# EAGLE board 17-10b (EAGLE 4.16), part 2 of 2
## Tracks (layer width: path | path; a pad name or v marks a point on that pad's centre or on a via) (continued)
S$881  (via drill 1 pad 1.78)
  other vias: 121.92,50.8
S$882  (via drill 1 pad 1.78)
  other vias: 124.46,50.8
S$883  (via drill 1 pad 1.78)
  other vias: 127,50.8
S$884  (via drill 1 pad 1.78)
  other vias: 129.54,50.8
S$885  (via drill 1 pad 1.78)
  other vias: 132.08,50.8
S$886  (via drill 1 pad 1.78)
  other vias: 134.62,50.8
S$887  (via drill 1 pad 1.78)
  other vias: 137.16,50.8
S$888  (via drill 1 pad 1.78)
  other vias: 139.7,50.8
S$889  (via drill 1 pad 1.78)
  other vias: 142.24,50.8
S$890  (via drill 1 pad 1.78)
  other vias: 144.78,50.8
S$891  (via drill 1 pad 1.78)
  other vias: 147.32,50.8
S$892  (via drill 1 pad 1.78)
  other vias: 152.4,50.8
S$893  (via drill 1 pad 1.78)
  other vias: 149.86,50.8
S$894  (via drill 1 pad 1.78)
  other vias: 154.94,50.8
S$895  (via drill 1 pad 1.78)
  other vias: 157.48,50.8
S$896  (via drill 1 pad 1.78)
  other vias: 157.48,48.26
S$897  (via drill 1 pad 1.78)
  other vias: 157.48,45.72
S$898  (via drill 1 pad 1.78)
  other vias: 157.48,43.18
S$899  (via drill 1 pad 1.78)
  other vias: 157.48,40.64
S$900  (via drill 1 pad 1.78)
  other vias: 157.48,38.1
S$901  (via drill 1 pad 1.78)
  other vias: 157.48,35.56
S$902  (via drill 1 pad 1.78)
  other vias: 157.48,33.02
S$903  (via drill 1 pad 1.78)
  other vias: 157.48,27.94
S$904  (via drill 1 pad 1.78)
  other vias: 157.48,30.48
S$905  (via drill 1 pad 1.78)
  other vias: 157.48,25.4
S$906  (via drill 1 pad 1.78)
  other vias: 157.48,22.86
S$907  (via drill 1 pad 1.78)
  other vias: 157.48,20.32
S$908  (via drill 1 pad 1.78)
  other vias: 157.48,17.78
S$909  (via drill 1 pad 1.78)
  other vias: 152.4,17.78
S$910  (via drill 1 pad 1.78)
  other vias: 154.94,17.78
S$911  (via drill 1 pad 1.78)
  other vias: 149.86,17.78
S$912  (via drill 1 pad 1.78)
  other vias: 147.32,17.78
S$913  (via drill 1 pad 1.78)
  other vias: 144.78,17.78
S$914  (via drill 1 pad 1.78)
  other vias: 139.7,17.78
S$915  (via drill 1 pad 1.78)
  other vias: 142.24,17.78
S$916  (via drill 1 pad 1.78)
  other vias: 17.78,48.26
S$917  (via drill 1 pad 1.78)
  other vias: 17.78,45.72
S$918  (via drill 1 pad 1.78)
  other vias: 17.78,43.18
S$919  (via drill 1 pad 1.78)
  other vias: 17.78,40.64
S$920  (via drill 1 pad 1.78)
  other vias: 17.78,38.1
S$921  (via drill 1 pad 1.78)
  other vias: 17.78,35.56
S$922  (via drill 1 pad 1.78)
  other vias: 17.78,30.48
S$923  (via drill 1 pad 1.78)
  other vias: 17.78,33.02
S$924  (via drill 1 pad 1.78)
  other vias: 17.78,27.94
S$925  (via drill 1 pad 1.78)
  other vias: 17.78,25.4
S$926  (via drill 1 pad 1.78)
  other vias: 17.78,22.86
S$927  (via drill 1 pad 1.78)
  other vias: 17.78,20.32
S$928  (via drill 1 pad 1.78)
  other vias: 17.78,17.78
S$929  (via drill 1 pad 1.78)
  other vias: 20.32,17.78
S$930  (via drill 1 pad 1.78)
  other vias: 22.86,17.78
S$931  (via drill 1 pad 1.78)
  other vias: 25.4,17.78
S$932  (via drill 1 pad 1.78)
  other vias: 27.94,17.78
S$933  (via drill 1 pad 1.78)
  other vias: 30.48,17.78
S$934  (via drill 1 pad 1.78)
  other vias: 33.02,17.78
S$935  (via drill 1 pad 1.78)
  other vias: 35.56,17.78
S$936  (via drill 1 pad 1.78)
  other vias: 38.1,17.78
S$937  (via drill 1 pad 1.78)
  other vias: 40.64,17.78
S$938  (via drill 1 pad 1.78)
  other vias: 43.18,17.78
S$939  (via drill 1 pad 1.78)
  other vias: 45.72,17.78
S$940  (via drill 1 pad 1.78)
  other vias: 50.8,17.78
S$941  (via drill 1 pad 1.78)
  other vias: 48.26,17.78
S$942  (via drill 1 pad 1.78)
  other vias: 53.34,17.78
S$943  (via drill 1 pad 1.78)
  other vias: 58.42,17.78
S$944  (via drill 1 pad 1.78)
  other vias: 55.88,17.78
S$945  (via drill 1 pad 1.78)
  other vias: 60.96,17.78
S$946  (via drill 1 pad 1.78)
  other vias: 63.5,17.78
S$947  (via drill 1 pad 1.78)
  other vias: 66.04,17.78
S$948  (via drill 1 pad 1.78)
  other vias: 71.12,17.78
S$949  (via drill 1 pad 1.78)
  other vias: 68.58,17.78
S$950  (via drill 1 pad 1.78)
  other vias: 73.66,17.78
S$951  (via drill 1 pad 1.78)
  other vias: 76.2,17.78
S$952  (via drill 1 pad 1.78)
  other vias: 78.74,17.78
S$953  (via drill 1 pad 1.78)
  other vias: 137.16,17.78
S$954  (via drill 1 pad 1.78)
  other vias: 134.62,17.78
S$955  (via drill 1 pad 1.78)
  other vias: 132.08,17.78
S$956  (via drill 1 pad 1.78)
  other vias: 129.54,17.78
S$957  (via drill 1 pad 1.78)
  other vias: 127,17.78
S$958  (via drill 1 pad 1.78)
  other vias: 124.46,17.78
S$959  (via drill 1 pad 1.78)
  other vias: 121.92,17.78
S$960  (via drill 1 pad 1.78)
  other vias: 119.38,17.78
S$961  (via drill 1 pad 1.78)
  other vias: 116.84,17.78
S$962  (via drill 1 pad 1.78)
  other vias: 114.3,17.78
S$963  (via drill 1 pad 1.78)
  other vias: 111.76,17.78
S$964  (via drill 1 pad 1.78)
  other vias: 106.68,17.78
S$965  (via drill 1 pad 1.78)
  other vias: 109.22,17.78
S$966  (via drill 1 pad 1.78)
  other vias: 104.14,17.78
S$967  (via drill 1 pad 1.78)
  other vias: 101.6,17.78
S$968  (via drill 1 pad 1.78)
  other vias: 99.06,17.78
S$969  (via drill 1 pad 1.78)
  other vias: 96.52,17.78
S$970  (via drill 1 pad 1.78)
  other vias: 93.98,17.78
S$971  (via drill 1 pad 1.78)
  other vias: 91.44,17.78
S$972  (via drill 1 pad 1.78)
  other vias: 88.9,17.78
S$973  (via drill 1 pad 1.78)
  other vias: 86.36,17.78
S$974  (via drill 1 pad 1.78)
  other vias: 83.82,17.78
S$975  (via drill 1 pad 1.78)
  other vias: 81.28,17.78
S$976  (via drill 1 pad 1.78)
  other vias: 154.94,48.26
S$977  (via drill 1 pad 1.78)
  other vias: 154.94,45.72
S$978  (via drill 1 pad 1.78)
  other vias: 154.94,43.18
S$979  (via drill 1 pad 1.78)
  other vias: 154.94,40.64
S$980  (via drill 1 pad 1.78)
  other vias: 154.94,38.1
S$981  (via drill 1 pad 1.78)
  other vias: 154.94,35.56
S$982  (via drill 1 pad 1.78)
  other vias: 154.94,33.02
S$983  (via drill 1 pad 1.78)
  other vias: 154.94,30.48
S$984  (via drill 1 pad 1.78)
  other vias: 154.94,27.94
S$985  (via drill 1 pad 1.78)
  other vias: 154.94,25.4
S$986  (via drill 1 pad 1.78)
  other vias: 154.94,22.86
S$987  (via drill 1 pad 1.78)
  other vias: 154.94,20.32
S$988  (via drill 1 pad 1.78)
  other vias: 48.26,45.72
S$989  (via drill 1 pad 1.78)
  other vias: 48.26,43.18
S$990  (via drill 1 pad 1.78)
  other vias: 48.26,33.02
S$991  (via drill 1 pad 1.78)
  other vias: 55.88,38.1
S$992  (via drill 1 pad 1.78)
  other vias: 60.96,38.1
S$993  (via drill 1 pad 1.78)
  other vias: 63.5,38.1
S$994  (via drill 1 pad 1.78)
  other vias: 66.04,38.1
S$995  (via drill 1 pad 1.78)
  other vias: 71.12,35.56
S$996  (via drill 1 pad 1.78)
  other vias: 86.36,33.02
S$997  (via drill 1 pad 1.78)
  other vias: 88.9,33.02
S$998  (via drill 1 pad 1.78)
  other vias: 91.44,35.56
S$999  (via drill 1 pad 1.78)
  other vias: 132.08,38.1
S$1000  (via drill 1 pad 1.78)
  other vias: 129.54,38.1
S$1001  (via drill 1 pad 1.78)
  other vias: 109.22,33.02
S$1002  (via drill 1 pad 1.78)
  other vias: 114.3,40.64
S$1003  (via drill 1 pad 1.78)
  other vias: 114.3,38.1
S$1004  (via drill 1 pad 1.78)
  other vias: 119.38,27.94
S$1005  (via drill 1 pad 1.78)
  other vias: 127,33.02
S$1006  (via drill 1 pad 1.78)
  other vias: 134.62,30.48
S$1007  (via drill 1 pad 1.78)
  other vias: 139.7,38.1
S$1008  (via drill 1 pad 1.78)
  other vias: 132.08,40.64
S$1009  (via drill 1 pad 1.78)
  other vias: 137.16,43.18
S$1010  (via drill 1 pad 1.78)
  other vias: 144.78,43.18
S$1011  (via drill 1 pad 1.78)
  other vias: 144.78,35.56
S$1012  (via drill 1 pad 1.78)
  other vias: 142.24,30.48
S$1013  (via drill 1 pad 1.78)
  other vias: 132.08,22.86
S$1014  (via drill 1 pad 1.78)
  other vias: 124.46,22.86
S$1015  (via drill 1 pad 1.78)
  other vias: 114.3,22.86
S$1016  (via drill 1 pad 1.78)
  other vias: 116.84,35.56
S$1017  (via drill 1 pad 1.78)
  other vias: 119.38,38.1
S$1018  (via drill 1 pad 1.78)
  other vias: 104.14,43.18
S$1019  (via drill 1 pad 1.78)
  other vias: 93.98,45.72
S$1020  (via drill 1 pad 1.78)
  other vias: 83.82,45.72
S$1021  (via drill 1 pad 1.78)
  other vias: 83.82,40.64
S$1022  (via drill 1 pad 1.78)
  other vias: 73.66,33.02
S$1023  (via drill 1 pad 1.78)
  other vias: 73.66,30.48
S$1024  (via drill 1 pad 1.78)
  other vias: 68.58,30.48
S$1025  (via drill 1 pad 1.78)
  other vias: 63.5,33.02
S$1026  (via drill 1 pad 1.78)
  other vias: 58.42,33.02
S$1027  (via drill 1 pad 1.78)
  other vias: 48.26,27.94
S$1028  (via drill 1 pad 1.78)
  other vias: 45.72,27.94
S$1029  (via drill 1 pad 1.78)
  other vias: 38.1,33.02
S$1030  (via drill 1 pad 1.78)
  other vias: 33.02,30.48
S$1031  (via drill 1 pad 1.78)
  other vias: 27.94,30.48
S$1032  (via drill 1 pad 1.78)
  other vias: 22.86,45.72
S$1033  (via drill 1 pad 1.78)
  other vias: 38.1,43.18
S$1034  (via drill 1 pad 1.78)
  other vias: 33.02,40.64
S$1035  (via drill 1 pad 1.78)
  other vias: 30.48,40.64
S$1036  (via drill 1 pad 1.78)
  other vias: 27.94,40.64
S$1037  (via drill 1 pad 1.78)
  other vias: 22.86,35.56
S$1038  (via drill 1 pad 1.78)
  other vias: 22.86,27.94
S$1039  (via drill 1 pad 1.78)
  other vias: 25.4,22.86
S$1040  (via drill 1 pad 1.78)
  other vias: 33.02,25.4
S$1041  (via drill 1 pad 1.78)
  other vias: 35.56,25.4
S$1042  (via drill 1 pad 1.78)
  other vias: 43.18,30.48
S$1043  (via drill 1 pad 1.78)
  other vias: 45.72,35.56
S$1044  (via drill 1 pad 1.78)
  other vias: 45.72,40.64
S$1045  (via drill 1 pad 1.78)
  other vias: 60.96,40.64
S$1046  (via drill 1 pad 1.78)
  other vias: 66.04,43.18
S$1047  (via drill 1 pad 1.78)
  other vias: 71.12,40.64
S$1048  (via drill 1 pad 1.78)
  other vias: 71.12,38.1
S$1049  (via drill 1 pad 1.78)
  other vias: 73.66,38.1
S$1050  (via drill 1 pad 1.78)
  other vias: 76.2,30.48
S$1051  (via drill 1 pad 1.78)
  other vias: 71.12,25.4
S$1052  (via drill 1 pad 1.78)
  other vias: 78.74,30.48
S$1053  (via drill 1 pad 1.78)
  other vias: 81.28,35.56
S$1054  (via drill 1 pad 1.78)
  other vias: 86.36,30.48
S$1055  (via drill 1 pad 1.78)
  other vias: 88.9,27.94
S$1056  (via drill 1 pad 1.78)
  other vias: 101.6,22.86
S$1057  (via drill 1 pad 1.78)
  other vias: 104.14,25.4
S$1058  (via drill 1 pad 1.78)
  other vias: 104.14,35.56
S$1059  (via drill 1 pad 1.78)
  other vias: 99.06,40.64
S$1060  (via drill 1 pad 1.78)
  other vias: 111.76,43.18
S$1061  (via drill 1 pad 1.78)
  other vias: 129.54,43.18
S$1062  (via drill 1 pad 1.78)
  other vias: 114.3,45.72
S$1063  (via drill 1 pad 1.78)
  other vias: 121.92,43.18
S$1064  (via drill 1 pad 1.78)
  other vias: 124.46,40.64
S$1065  (via drill 1 pad 1.78)
  other vias: 124.46,38.1
S$1066  (via drill 1 pad 1.78)
  other vias: 121.92,33.02
S$1067  (via drill 1 pad 1.78)
  other vias: 124.46,27.94
S$1068  (via drill 1 pad 1.78)
  other vias: 127,27.94
S$1069  (via drill 1 pad 1.78)
  other vias: 129.54,27.94
S$1070  (via drill 1 pad 1.78)
  other vias: 134.62,33.02
S$1071  (via drill 1 pad 1.78)
  other vias: 139.7,33.02
S$1072  (via drill 1 pad 1.78)
  other vias: 144.78,33.02
S$1073  (via drill 1 pad 1.78)
  other vias: 149.86,40.64
S$1074  (via drill 1 pad 1.78)
  other vias: 147.32,27.94
S$1075  (via drill 1 pad 1.78)
  other vias: 142.24,25.4
S$1076  (via drill 1 pad 1.78)
  other vias: 142.24,22.86
S$1077  (via drill 1 pad 1.78)
  other vias: 144.78,22.86
S$1078  (via drill 1 pad 1.78)
  other vias: 147.32,25.4
S$1079  (via drill 1 pad 1.78)
  other vias: 152.4,33.02
S$1080  (via drill 1 pad 1.78)
  other vias: 149.86,35.56
S$1081  (via drill 1 pad 1.78)
  other vias: 134.62,45.72
S$1082  (via drill 1 pad 1.78)
  other vias: 124.46,48.26
S$1083  (via drill 1 pad 1.78)
  other vias: 114.3,48.26
S$1084  (via drill 1 pad 1.78)
  other vias: 106.68,48.26
S$1085  (via drill 1 pad 1.78)
  other vias: 99.06,48.26
S$1086  (via drill 1 pad 1.78)
  other vias: 88.9,45.72
S$1087  (via drill 1 pad 1.78)
  other vias: 88.9,43.18
S$1088  (via drill 1 pad 1.78)
  other vias: 86.36,38.1
S$1089  (via drill 1 pad 1.78)
  other vias: 83.82,35.56
S$1090  (via drill 1 pad 1.78)
  other vias: 81.28,27.94
S$1091  (via drill 1 pad 1.78)
  other vias: 78.74,27.94
S$1092  (via drill 1 pad 1.78)
  other vias: 76.2,25.4
S$1093  (via drill 1 pad 1.78)
  other vias: 68.58,25.4
S$1094  (via drill 1 pad 1.78)
  other vias: 60.96,22.86
S$1095  (via drill 1 pad 1.78)
  other vias: 58.42,22.86
S$1096  (via drill 1 pad 1.78)
  other vias: 55.88,25.4
S$1097  (via drill 1 pad 1.78)
  other vias: 55.88,27.94
S$1098  (via drill 1 pad 1.78)
  other vias: 53.34,33.02
S$1099  (via drill 1 pad 1.78)
  other vias: 53.34,40.64
S$1100  (via drill 1 pad 1.78)
  other vias: 55.88,43.18
S$1101  (via drill 1 pad 1.78)
  other vias: 58.42,43.18
S$1102  (via drill 1 pad 1.78)
  other vias: 58.42,45.72
S$1103  (via drill 1 pad 1.78)
  other vias: 53.34,48.26
S$1104  (via drill 1 pad 1.78)
  other vias: 48.26,48.26
S$1105  (via drill 1 pad 1.78)
  other vias: 43.18,48.26
S$1106  (via drill 1 pad 1.78)
  other vias: 40.64,48.26
S$1107  (via drill 1 pad 1.78)
  other vias: 27.94,45.72
S$1108  (via drill 1 pad 1.78)
  other vias: 30.48,45.72
S$1109  (via drill 1 pad 1.78)
  other vias: 33.02,45.72
S$1110  (via drill 1 pad 1.78)
  other vias: 38.1,38.1
S$1111  (via drill 1 pad 1.78)
  other vias: 27.94,38.1
S$1112  (via drill 1 pad 1.78)
  other vias: 25.4,43.18
S$1113  (via drill 1 pad 1.78)
  other vias: 22.86,40.64
S$1114  (via drill 1 pad 1.78)
  other vias: 25.4,38.1
S$1115  (via drill 1 pad 1.78)
  other vias: 25.4,30.48
S$1116  (via drill 1 pad 1.78)
  other vias: 27.94,22.86
S$1117  (via drill 1 pad 1.78)
  other vias: 30.48,20.32
S$1118  (via drill 1 pad 1.78)
  other vias: 38.1,27.94
S$1119  (via drill 1 pad 1.78)
  other vias: 40.64,25.4
S$1120  (via drill 1 pad 1.78)
  other vias: 45.72,22.86
S$1121  (via drill 1 pad 1.78)
  other vias: 40.64,20.32
S$1122  (via drill 1 pad 1.78)
  other vias: 53.34,22.86
S$1123  (via drill 1 pad 1.78)
  other vias: 45.72,20.32
S$1124  (via drill 1 pad 1.78)
  other vias: 35.56,22.86
S$1125  (via drill 1 pad 1.78)
  other vias: 38.1,22.86
S$1126  (via drill 1 pad 1.78)
  other vias: 48.26,25.4
S$1127  (via drill 1 pad 1.78)
  other vias: 63.5,22.86
S$1128  (via drill 1 pad 1.78)
  other vias: 68.58,22.86
S$1129  (via drill 1 pad 1.78)
  other vias: 71.12,22.86
S$1130  (via drill 1 pad 1.78)
  other vias: 66.04,27.94
S$1131  (via drill 1 pad 1.78)
  other vias: 93.98,22.86
S$1132  (via drill 1 pad 1.78)
  other vias: 96.52,25.4
S$1133  (via drill 1 pad 1.78)
  other vias: 104.14,27.94
S$1134  (via drill 1 pad 1.78)
  other vias: 114.3,27.94
S$1135  (via drill 1 pad 1.78)
  other vias: 111.76,27.94
S$1136  (via drill 1 pad 1.78)
  other vias: 104.14,22.86
S$1137  (via drill 1 pad 1.78)
  other vias: 109.22,25.4
S$1138  (via drill 1 pad 1.78)
  other vias: 109.22,22.86
S$1139  (via drill 1 pad 1.78)
  other vias: 121.92,25.4
S$1140  (via drill 1 pad 1.78)
  other vias: 119.38,22.86
S$1141  (via drill 1 pad 1.78)
  other vias: 137.16,25.4
S$1142  (via drill 1 pad 1.78)
  other vias: 134.62,22.86
S$1143  (via drill 1 pad 1.78)
  other vias: 129.54,25.4
S$1144  (via drill 1 pad 1.78)
  other vias: 127,22.86
S$1145  (via drill 1 pad 1.78)
  other vias: 137.16,22.86
S$1146  (via drill 1 pad 1.78)
  other vias: 149.86,22.86
S$1147  (via drill 1 pad 1.78)
  other vias: 152.4,45.72
S$1148  (via drill 1 pad 1.78)
  other vias: 149.86,45.72
S$1149  (via drill 1 pad 1.78)
  other vias: 147.32,45.72
S$1150  (via drill 1 pad 1.78)
  other vias: 144.78,45.72
S$1151  (via drill 1 pad 1.78)
  other vias: 139.7,48.26
S$1152  (via drill 1 pad 1.78)
  other vias: 109.22,38.1
S$1153  (via drill 1 pad 1.78)
  other vias: 114.3,33.02
S$1154  (via drill 1 pad 1.78)
  other vias: 116.84,30.48
S$1155  (via drill 1 pad 1.78)
  other vias: 132.08,33.02
S$1156  (via drill 1 pad 1.78)
  other vias: 137.16,38.1
S$1157  (via drill 1 pad 1.78)
  other vias: 142.24,43.18
S$1158  (via drill 1 pad 1.78)
  other vias: 147.32,38.1
S$1159  (via drill 1 pad 1.78)
  other vias: 152.4,30.48
S$1160  (via drill 1 pad 1.78)
  other vias: 149.86,30.48
S$1161  (via drill 1 pad 1.78)
  other vias: 152.4,25.4
S$1162  (via drill 1 pad 1.78)
  other vias: 129.54,45.72
S$1163  (via drill 1 pad 1.78)
  other vias: 119.38,45.72
S$1164  (via drill 1 pad 1.78)
  other vias: 116.84,43.18
S$1165  (via drill 1 pad 1.78)
  other vias: 106.68,40.64
S$1166  (via drill 1 pad 1.78)
  other vias: 104.14,38.1
S$1167  (via drill 1 pad 1.78)
  other vias: 99.06,45.72
S$1168  (via drill 1 pad 1.78)
  other vias: 93.98,48.26
S$1169  (via drill 1 pad 1.78)
  other vias: 88.9,48.26
S$1170  (via drill 1 pad 1.78)
  other vias: 81.28,48.26
S$1171  (via drill 1 pad 1.78)
  other vias: 78.74,45.72
S$1172  (via drill 1 pad 1.78)
  other vias: 76.2,40.64
S$1173  (via drill 1 pad 1.78)
  other vias: 76.2,35.56
S$1174  (via drill 1 pad 1.78)
  other vias: 78.74,38.1
S$1175  (via drill 1 pad 1.78)
  other vias: 73.66,43.18
S$1176  (via drill 1 pad 1.78)
  other vias: 73.66,45.72
S$1177  (via drill 1 pad 1.78)
  other vias: 71.12,45.72
S$1178  (via drill 1 pad 1.78)
  other vias: 68.58,45.72
S$1179  (via drill 1 pad 1.78)
  other vias: 60.96,45.72
S$1180  (via drill 1 pad 1.78)
  other vias: 50.8,38.1
S$1181  (via drill 1 pad 1.78)
  other vias: 50.8,43.18
S$1182  (via drill 1 pad 1.78)
  other vias: 50.8,33.02
S$1183  (via drill 1 pad 1.78)
  other vias: 50.8,27.94
S$1184  (via drill 1 pad 1.78)
  other vias: 43.18,43.18
S$1185  (via drill 1 pad 1.78)
  other vias: 43.18,35.56
S$1186  (via drill 1 pad 1.78)
  other vias: 40.64,33.02
S$1187  (via drill 1 pad 1.78)
  other vias: 35.56,40.64
S$1188  (via drill 1 pad 1.78)
  other vias: 35.56,45.72
S$1189  (via drill 1 pad 1.78)
  other vias: 152.4,20.32
S$1190  (via drill 1 pad 1.78)
  other vias: 149.86,20.32
S$1191  (via drill 1 pad 1.78)
  other vias: 147.32,20.32
S$1192  (via drill 1 pad 1.78)
  other vias: 139.7,20.32
S$1193  (via drill 1 pad 1.78)
  other vias: 134.62,20.32
S$1194  (via drill 1 pad 1.78)
  other vias: 132.08,20.32
S$1195  (via drill 1 pad 1.78)
  other vias: 127,20.32
S$1196  (via drill 1 pad 1.78)
  other vias: 124.46,20.32
S$1197  (via drill 1 pad 1.78)
  other vias: 114.3,20.32
S$1198  (via drill 1 pad 1.78)
  other vias: 111.76,20.32
S$1199  (via drill 1 pad 1.78)
  other vias: 104.14,20.32
S$1200  (via drill 1 pad 1.78)
  other vias: 99.06,20.32
S$1201  (via drill 1 pad 1.78)
  other vias: 93.98,20.32
S$1202  (via drill 1 pad 1.78)
  other vias: 91.44,20.32
S$1203  (via drill 1 pad 1.78)
  other vias: 88.9,20.32
S$1204  (via drill 1 pad 1.78)
  other vias: 86.36,20.32
S$1205  (via drill 1 pad 1.78)
  other vias: 83.82,20.32
S$1206  (via drill 1 pad 1.78)
  other vias: 81.28,20.32
S$1207  (via drill 1 pad 1.78)
  other vias: 48.26,20.32
S$1208  (via drill 1 pad 1.78)
  other vias: 50.8,20.32
S$1209  (via drill 1 pad 1.78)
  other vias: 53.34,20.32
S$1210  (via drill 1 pad 1.78)
  other vias: 58.42,20.32
S$1211  (via drill 1 pad 1.78)
  other vias: 60.96,20.32
S$1212  (via drill 1 pad 1.78)
  other vias: 63.5,20.32
S$1213  (via drill 1 pad 1.78)
  other vias: 66.04,20.32
S$1214  (via drill 1 pad 1.78)
  other vias: 68.58,20.32
S$1215  (via drill 1 pad 1.78)
  other vias: 73.66,20.32
S$1216  (via drill 1 pad 1.78)
  other vias: 76.2,20.32
S$1217  (via drill 1 pad 1.78)
  other vias: 78.74,22.86
S$1218  (via drill 1 pad 1.78)
  other vias: 83.82,25.4
S$1219  (via drill 1 pad 1.78)
  other vias: 86.36,27.94
S$1220  (via drill 1 pad 1.78)
  other vias: 91.44,25.4
S$1221  (via drill 1 pad 1.78)
  other vias: 91.44,30.48
S$1222  (via drill 1 pad 1.78)
  other vias: 93.98,33.02
S$1223  (via drill 1 pad 1.78)
  other vias: 96.52,35.56
S$1224  (via drill 1 pad 1.78)
  other vias: 101.6,27.94
S$1225  (via drill 1 pad 1.78)
  other vias: 101.6,30.48
S$1226  (via drill 1 pad 1.78)
  other vias: 101.6,33.02
S$1227  (via drill 1 pad 1.78)
  other vias: 106.68,30.48
S$1228  (via drill 1 pad 1.78)
  other vias: 106.68,27.94
S$1229  (via drill 1 pad 1.78)
  other vias: 106.68,25.4
S$1230  (via drill 1 pad 1.78)
  other vias: 109.22,20.32
S$1231  (via drill 1 pad 1.78)
  other vias: 114.3,25.4
S$1232  (via drill 1 pad 1.78)
  other vias: 111.76,22.86
S$1233  (via drill 1 pad 1.78)
  other vias: 111.76,25.4
S$1234  (via drill 1 pad 1.78)
  other vias: 116.84,25.4
S$1235  (via drill 1 pad 1.78)
  other vias: 116.84,20.32
S$1236  (via drill 1 pad 1.78)
  other vias: 116.84,22.86
S$1237  (via drill 1 pad 1.78)
  other vias: 119.38,20.32
S$1238  (via drill 1 pad 1.78)
  other vias: 121.92,20.32
S$1239  (via drill 1 pad 1.78)
  other vias: 121.92,22.86
S$1240  (via drill 1 pad 1.78)
  other vias: 129.54,22.86
S$1241  (via drill 1 pad 1.78)
  other vias: 129.54,20.32
S$1242  (via drill 1 pad 1.78)
  other vias: 137.16,20.32
S$1243  (via drill 1 pad 1.78)
  other vias: 142.24,20.32
S$1244  (via drill 1 pad 1.78)
  other vias: 144.78,20.32
S$1245  (via drill 1 pad 1.78)
  other vias: 152.4,22.86
S$1246  (via drill 1 pad 1.78)
  other vias: 152.4,27.94
S$1247  (via drill 1 pad 1.78)
  other vias: 152.4,48.26
S$1248  (via drill 1 pad 1.78)
  other vias: 152.4,43.18
S$1249  (via drill 1 pad 1.78)
  other vias: 152.4,40.64
S$1250  (via drill 1 pad 1.78)
  other vias: 152.4,38.1
S$1251  (via drill 1 pad 1.78)
  other vias: 152.4,35.56
S$1252  (via drill 1 pad 1.78)
  other vias: 149.86,48.26
S$1253  (via drill 1 pad 1.78)
  other vias: 147.32,48.26
S$1254  (via drill 1 pad 1.78)
  other vias: 144.78,48.26
S$1255  (via drill 1 pad 1.78)
  other vias: 142.24,48.26
S$1256  (via drill 1 pad 1.78)
  other vias: 137.16,48.26
S$1257  (via drill 1 pad 1.78)
  other vias: 134.62,48.26
S$1258  (via drill 1 pad 1.78)
  other vias: 129.54,48.26
S$1259  (via drill 1 pad 1.78)
  other vias: 127,48.26
S$1260  (via drill 1 pad 1.78)
  other vias: 121.92,48.26
S$1261  (via drill 1 pad 1.78)
  other vias: 119.38,48.26
S$1262  (via drill 1 pad 1.78)
  other vias: 116.84,48.26
S$1263  (via drill 1 pad 1.78)
  other vias: 116.84,45.72
S$1264  (via drill 1 pad 1.78)
  other vias: 116.84,40.64
S$1265  (via drill 1 pad 1.78)
  other vias: 116.84,38.1
S$1266  (via drill 1 pad 1.78)
  other vias: 119.38,43.18
S$1267  (via drill 1 pad 1.78)
  other vias: 121.92,40.64
S$1268  (via drill 1 pad 1.78)
  other vias: 119.38,40.64
S$1269  (via drill 1 pad 1.78)
  other vias: 124.46,45.72
S$1270  (via drill 1 pad 1.78)
  other vias: 121.92,45.72
S$1271  (via drill 1 pad 1.78)
  other vias: 127,45.72
S$1272  (via drill 1 pad 1.78)
  other vias: 124.46,43.18
S$1273  (via drill 1 pad 1.78)
  other vias: 127,43.18
S$1274  (via drill 1 pad 1.78)
  other vias: 127,40.64
S$1275  (via drill 1 pad 1.78)
  other vias: 127,38.1
S$1276  (via drill 1 pad 1.78)
  other vias: 20.32,48.26
S$1277  (via drill 1 pad 1.78)
  other vias: 20.32,45.72
S$1278  (via drill 1 pad 1.78)
  other vias: 20.32,43.18
S$1279  (via drill 1 pad 1.78)
  other vias: 20.32,40.64
S$1280  (via drill 1 pad 1.78)
  other vias: 20.32,38.1
S$1281  (via drill 1 pad 1.78)
  other vias: 20.32,35.56
S$1282  (via drill 1 pad 1.78)
  other vias: 20.32,33.02
S$1283  (via drill 1 pad 1.78)
  other vias: 20.32,30.48
S$1284  (via drill 1 pad 1.78)
  other vias: 20.32,27.94
S$1285  (via drill 1 pad 1.78)
  other vias: 20.32,25.4
S$1286  (via drill 1 pad 1.78)
  other vias: 20.32,22.86
S$1287  (via drill 1 pad 1.78)
  other vias: 20.32,20.32
S$1288  (via drill 1 pad 1.78)
  other vias: 22.86,20.32
S$1289  (via drill 1 pad 1.78)
  other vias: 25.4,20.32
S$1290  (via drill 1 pad 1.78)
  other vias: 27.94,20.32
S$1291  (via drill 1 pad 1.78)
  other vias: 22.86,22.86
S$1292  (via drill 1 pad 1.78)
  other vias: 22.86,33.02
S$1293  (via drill 1 pad 1.78)
  other vias: 22.86,25.4
S$1294  (via drill 1 pad 1.78)
  other vias: 22.86,30.48
S$1295  (via drill 1 pad 1.78)
  other vias: 22.86,38.1
S$1296  (via drill 1 pad 1.78)
  other vias: 22.86,43.18
S$1297  (via drill 1 pad 1.78)
  other vias: 22.86,48.26
S$1298  (via drill 1 pad 1.78)
  other vias: 27.94,48.26
S$1299  (via drill 1 pad 1.78)
  other vias: 30.48,48.26
S$1300  (via drill 1 pad 1.78)
  other vias: 33.02,48.26
S$1301  (via drill 1 pad 1.78)
  other vias: 35.56,48.26
S$1302  (via drill 1 pad 1.78)
  other vias: 27.94,43.18
S$1303  (via drill 1 pad 1.78)
  other vias: 25.4,40.64
S$1304  (via drill 1 pad 1.78)
  other vias: 25.4,35.56
S$1305  (via drill 1 pad 1.78)
  other vias: 25.4,33.02
S$1306  (via drill 1 pad 1.78)
  other vias: 25.4,27.94
S$1307  (via drill 1 pad 1.78)
  other vias: 25.4,25.4
S$1308  (via drill 1 pad 1.78)
  other vias: 27.94,25.4
S$1309  (via drill 1 pad 1.78)
  other vias: 27.94,27.94
S$1310  (via drill 1 pad 1.78)
  other vias: 27.94,35.56
S$1311  (via drill 1 pad 1.78)
  other vias: 30.48,38.1
S$1312  (via drill 1 pad 1.78)
  other vias: 30.48,43.18
S$1313  (via drill 1 pad 1.78)
  other vias: 33.02,43.18
S$1314  (via drill 1 pad 1.78)
  other vias: 35.56,43.18
S$1315  (via drill 1 pad 1.78)
  other vias: 33.02,38.1
S$1316  (via drill 1 pad 1.78)
  other vias: 35.56,38.1
S$1317  (via drill 1 pad 1.78)
  other vias: 33.02,35.56
S$1318  (via drill 1 pad 1.78)
  other vias: 30.48,35.56
S$1319  (via drill 1 pad 1.78)
  other vias: 35.56,33.02
S$1320  (via drill 1 pad 1.78)
  other vias: 33.02,33.02
S$1321  (via drill 1 pad 1.78)
  other vias: 30.48,30.48
S$1322  (via drill 1 pad 1.78)
  other vias: 30.48,27.94
S$1323  (via drill 1 pad 1.78)
  other vias: 30.48,25.4
S$1324  (via drill 1 pad 1.78)
  other vias: 30.48,22.86
S$1325  (via drill 1 pad 1.78)
  other vias: 33.02,20.32
S$1326  (via drill 1 pad 1.78)
  other vias: 35.56,20.32
S$1327  (via drill 1 pad 1.78)
  other vias: 38.1,20.32
S$1328  (via drill 1 pad 1.78)
  other vias: 33.02,22.86
S$1329  (via drill 1 pad 1.78)
  other vias: 33.02,27.94
S$1330  (via drill 1 pad 1.78)
  other vias: 35.56,27.94
S$1331  (via drill 1 pad 1.78)
  other vias: 35.56,30.48
S$1332  (via drill 1 pad 1.78)
  other vias: 38.1,30.48
S$1333  (via drill 1 pad 1.78)
  other vias: 40.64,30.48
S$1334  (via drill 1 pad 1.78)
  other vias: 40.64,27.94
S$1335  (via drill 1 pad 1.78)
  other vias: 43.18,27.94
S$1336  (via drill 1 pad 1.78)
  other vias: 43.18,25.4
S$1337  (via drill 1 pad 1.78)
  other vias: 45.72,25.4
S$1338  (via drill 1 pad 1.78)
  other vias: 43.18,22.86
S$1339  (via drill 1 pad 1.78)
  other vias: 43.18,20.32
S$1340  (via drill 1 pad 1.78)
  other vias: 40.64,22.86
S$1341  (via drill 1 pad 1.78)
  other vias: 38.1,25.4
S$1342  (via drill 1 pad 1.78)
  other vias: 38.1,48.26
S$1343  (via drill 1 pad 1.78)
  other vias: 38.1,45.72
S$1344  (via drill 1 pad 1.78)
  other vias: 38.1,40.64
S$1345  (via drill 1 pad 1.78)
  other vias: 38.1,35.56
S$1346  (via drill 1 pad 1.78)
  other vias: 40.64,45.72
S$1347  (via drill 1 pad 1.78)
  other vias: 40.64,43.18
S$1348  (via drill 1 pad 1.78)
  other vias: 45.72,48.26
S$1349  (via drill 1 pad 1.78)
  other vias: 55.88,48.26
S$1350  (via drill 1 pad 1.78)
  other vias: 50.8,48.26
S$1351  (via drill 1 pad 1.78)
  other vias: 45.72,45.72
S$1352  (via drill 1 pad 1.78)
  other vias: 43.18,45.72
S$1353  (via drill 1 pad 1.78)
  other vias: 45.72,43.18
S$1354  (via drill 1 pad 1.78)
  other vias: 43.18,40.64
S$1355  (via drill 1 pad 1.78)
  other vias: 40.64,40.64
S$1356  (via drill 1 pad 1.78)
  other vias: 43.18,38.1
S$1357  (via drill 1 pad 1.78)
  other vias: 40.64,35.56
S$1358  (via drill 1 pad 1.78)
  other vias: 43.18,33.02
S$1359  (via drill 1 pad 1.78)
  other vias: 45.72,33.02
S$1360  (via drill 1 pad 1.78)
  other vias: 45.72,38.1
S$1361  (via drill 1 pad 1.78)
  other vias: 58.42,48.26
S$1362  (via drill 1 pad 1.78)
  other vias: 63.5,48.26
S$1363  (via drill 1 pad 1.78)
  other vias: 60.96,48.26
S$1364  (via drill 1 pad 1.78)
  other vias: 66.04,48.26
S$1365  (via drill 1 pad 1.78)
  other vias: 68.58,48.26
S$1366  (via drill 1 pad 1.78)
  other vias: 73.66,48.26
S$1367  (via drill 1 pad 1.78)
  other vias: 76.2,48.26
S$1368  (via drill 1 pad 1.78)
  other vias: 78.74,48.26
S$1369  (via drill 1 pad 1.78)
  other vias: 83.82,48.26
S$1370  (via drill 1 pad 1.78)
  other vias: 86.36,48.26
S$1371  (via drill 1 pad 1.78)
  other vias: 86.36,45.72
S$1372  (via drill 1 pad 1.78)
  other vias: 86.36,43.18
S$1373  (via drill 1 pad 1.78)
  other vias: 86.36,40.64
S$1374  (via drill 1 pad 1.78)
  other vias: 83.82,43.18
S$1375  (via drill 1 pad 1.78)
  other vias: 81.28,43.18
S$1376  (via drill 1 pad 1.78)
  other vias: 81.28,45.72
S$1377  (via drill 1 pad 1.78)
  other vias: 76.2,45.72
S$1378  (via drill 1 pad 1.78)
  other vias: 78.74,43.18
S$1379  (via drill 1 pad 1.78)
  other vias: 76.2,43.18
S$1380  (via drill 1 pad 1.78)
  other vias: 71.12,43.18
S$1381  (via drill 1 pad 1.78)
  other vias: 68.58,43.18
S$1382  (via drill 1 pad 1.78)
  other vias: 66.04,45.72
S$1383  (via drill 1 pad 1.78)
  other vias: 63.5,45.72
S$1384  (via drill 1 pad 1.78)
  other vias: 63.5,43.18
S$1385  (via drill 1 pad 1.78)
  other vias: 60.96,43.18
S$1386  (via drill 1 pad 1.78)
  other vias: 55.88,45.72
S$1387  (via drill 1 pad 1.78)
  other vias: 53.34,45.72
S$1388  (via drill 1 pad 1.78)
  other vias: 50.8,45.72
S$1389  (via drill 1 pad 1.78)
  other vias: 53.34,43.18
S$1390  (via drill 1 pad 1.78)
  other vias: 48.26,40.64
S$1391  (via drill 1 pad 1.78)
  other vias: 48.26,38.1
S$1392  (via drill 1 pad 1.78)
  other vias: 48.26,35.56
S$1393  (via drill 1 pad 1.78)
  other vias: 50.8,35.56
S$1394  (via drill 1 pad 1.78)
  other vias: 53.34,35.56
S$1395  (via drill 1 pad 1.78)
  other vias: 58.42,35.56
S$1396  (via drill 1 pad 1.78)
  other vias: 66.04,35.56
S$1397  (via drill 1 pad 1.78)
  other vias: 139.7,22.86
S$1398  (via drill 1 pad 1.78)
  other vias: 147.32,22.86
S$1399  (via drill 1 pad 1.78)
  other vias: 149.86,25.4
S$1400  (via drill 1 pad 1.78)
  other vias: 149.86,27.94
S$1401  (via drill 1 pad 1.78)
  other vias: 144.78,25.4
S$1402  (via drill 1 pad 1.78)
  other vias: 144.78,27.94
S$1403  (via drill 1 pad 1.78)
  other vias: 147.32,30.48
S$1404  (via drill 1 pad 1.78)
  other vias: 149.86,33.02
S$1405  (via drill 1 pad 1.78)
  other vias: 147.32,33.02
S$1406  (via drill 1 pad 1.78)
  other vias: 147.32,35.56
S$1407  (via drill 1 pad 1.78)
  other vias: 149.86,38.1
S$1408  (via drill 1 pad 1.78)
  other vias: 149.86,43.18
S$1409  (via drill 1 pad 1.78)
  other vias: 147.32,43.18
S$1410  (via drill 1 pad 1.78)
  other vias: 147.32,40.64
S$1411  (via drill 1 pad 1.78)
  other vias: 144.78,40.64
S$1412  (via drill 1 pad 1.78)
  other vias: 142.24,40.64
S$1413  (via drill 1 pad 1.78)
  other vias: 91.44,48.26
S$1414  (via drill 1 pad 1.78)
  other vias: 96.52,48.26
S$1415  (via drill 1 pad 1.78)
  other vias: 101.6,48.26
S$1416  (via drill 1 pad 1.78)
  other vias: 104.14,48.26
S$1417  (via drill 1 pad 1.78)
  other vias: 101.6,45.72
S$1418  (via drill 1 pad 1.78)
  other vias: 101.6,40.64
S$1419  (via drill 1 pad 1.78)
  other vias: 101.6,38.1
S$1420  (via drill 1 pad 1.78)
  other vias: 99.06,38.1
S$1421  (via drill 1 pad 1.78)
  other vias: 96.52,38.1
S$1422  (via drill 1 pad 1.78)
  other vias: 93.98,38.1
S$1423  (via drill 1 pad 1.78)
  other vias: 91.44,38.1
S$1424  (via drill 1 pad 1.78)
  other vias: 88.9,40.64
S$1425  (via drill 1 pad 1.78)
  other vias: 91.44,40.64
S$1426  (via drill 1 pad 1.78)
  other vias: 91.44,43.18
S$1427  (via drill 1 pad 1.78)
  other vias: 93.98,43.18
S$1428  (via drill 1 pad 1.78)
  other vias: 96.52,43.18
S$1429  (via drill 1 pad 1.78)
  other vias: 99.06,43.18
S$1430  (via drill 1 pad 1.78)
  other vias: 101.6,43.18
S$1431  (via drill 1 pad 1.78)
  other vias: 109.22,48.26
S$1432  (via drill 1 pad 1.78)
  other vias: 109.22,45.72
S$1433  (via drill 1 pad 1.78)
  other vias: 109.22,43.18
S$1434  (via drill 1 pad 1.78)
  other vias: 109.22,40.64
S$1435  (via drill 1 pad 1.78)
  other vias: 111.76,40.64
S$1436  (via drill 1 pad 1.78)
  other vias: 111.76,38.1
S$1437  (via drill 1 pad 1.78)
  other vias: 111.76,35.56
S$1438  (via drill 1 pad 1.78)
  other vias: 111.76,30.48
S$1439  (via drill 1 pad 1.78)
  other vias: 111.76,33.02
S$1440  (via drill 1 pad 1.78)
  other vias: 76.2,33.02
S$1441  (via drill 1 pad 1.78)
  other vias: 78.74,33.02
S$1442  (via drill 1 pad 1.78)
  other vias: 81.28,33.02
S$1443  (via drill 1 pad 1.78)
  other vias: 83.82,33.02
S$1444  (via drill 1 pad 1.78)
  other vias: 83.82,30.48
S$1445  (via drill 1 pad 1.78)
  other vias: 83.82,27.94
S$1446  (via drill 1 pad 1.78)
  other vias: 45.72,30.48
S$1447  (via drill 1 pad 1.78)
  other vias: 48.26,30.48
S$1448  (via drill 1 pad 1.78)
  other vias: 50.8,30.48
S$1449  (via drill 1 pad 1.78)
  other vias: 53.34,30.48
S$1450  (via drill 1 pad 1.78)
  other vias: 58.42,30.48
S$1451  (via drill 1 pad 1.78)
  other vias: 60.96,30.48
S$1452  (via drill 1 pad 1.78)
  other vias: 63.5,30.48
S$1453  (via drill 1 pad 1.78)
  other vias: 66.04,30.48
S$1454  (via drill 1 pad 1.78)
  other vias: 55.88,30.48
S$1455  (via drill 1 pad 1.78)
  other vias: 55.88,33.02
S$1456  (via drill 1 pad 1.78)
  other vias: 58.42,40.64
S$1457  (via drill 1 pad 1.78)
  other vias: 55.88,40.64
S$1458  (via drill 1 pad 1.78)
  other vias: 50.8,40.64
S$1459  (via drill 1 pad 1.78)
  other vias: 53.34,38.1
S$1460  (via drill 1 pad 1.78)
  other vias: 58.42,38.1
S$1461  (via drill 1 pad 1.78)
  other vias: 63.5,40.64
S$1462  (via drill 1 pad 1.78)
  other vias: 66.04,40.64
S$1463  (via drill 1 pad 1.78)
  other vias: 68.58,40.64
S$1464  (via drill 1 pad 1.78)
  other vias: 68.58,38.1
S$1465  (via drill 1 pad 1.78)
  other vias: 68.58,35.56
S$1466  (via drill 1 pad 1.78)
  other vias: 48.26,22.86
S$1467  (via drill 1 pad 1.78)
  other vias: 50.8,22.86
S$1468  (via drill 1 pad 1.78)
  other vias: 50.8,25.4
S$1469  (via drill 1 pad 1.78)
  other vias: 53.34,25.4
S$1470  (via drill 1 pad 1.78)
  other vias: 53.34,27.94
S$1471  (via drill 1 pad 1.78)
  other vias: 55.88,35.56
S$1472  (via drill 1 pad 1.78)
  other vias: 55.88,22.86
S$1473  (via drill 1 pad 1.78)
  other vias: 55.88,20.32
S$1474  (via drill 1 pad 1.78)
  other vias: 58.42,25.4
S$1475  (via drill 1 pad 1.78)
  other vias: 60.96,25.4
S$1476  (via drill 1 pad 1.78)
  other vias: 63.5,25.4
S$1477  (via drill 1 pad 1.78)
  other vias: 66.04,25.4
S$1478  (via drill 1 pad 1.78)
  other vias: 66.04,22.86
S$1479  (via drill 1 pad 1.78)
  other vias: 63.5,27.94
S$1480  (via drill 1 pad 1.78)
  other vias: 58.42,27.94
S$1481  (via drill 1 pad 1.78)
  other vias: 60.96,33.02
S$1482  (via drill 1 pad 1.78)
  other vias: 60.96,35.56
S$1483  (via drill 1 pad 1.78)
  other vias: 63.5,35.56
S$1484  (via drill 1 pad 1.78)
  other vias: 66.04,33.02
S$1485  (via drill 1 pad 1.78)
  other vias: 68.58,33.02
S$1486  (via drill 1 pad 1.78)
  other vias: 71.12,33.02
S$1487  (via drill 1 pad 1.78)
  other vias: 71.12,30.48
S$1488  (via drill 1 pad 1.78)
  other vias: 71.12,27.94
S$1489  (via drill 1 pad 1.78)
  other vias: 68.58,27.94
S$1490  (via drill 1 pad 1.78)
  other vias: 71.12,20.32
S$1491  (via drill 1 pad 1.78)
  other vias: 73.66,22.86
S$1492  (via drill 1 pad 1.78)
  other vias: 76.2,22.86
S$1493  (via drill 1 pad 1.78)
  other vias: 73.66,25.4
S$1494  (via drill 1 pad 1.78)
  other vias: 73.66,27.94
S$1495  (via drill 1 pad 1.78)
  other vias: 76.2,27.94
S$1496  (via drill 1 pad 1.78)
  other vias: 73.66,35.56
S$1497  (via drill 1 pad 1.78)
  other vias: 73.66,40.64
S$1498  (via drill 1 pad 1.78)
  other vias: 76.2,38.1
S$1499  (via drill 1 pad 1.78)
  other vias: 78.74,40.64
S$1500  (via drill 1 pad 1.78)
  other vias: 78.74,35.56
S$1501  (via drill 1 pad 1.78)
  other vias: 81.28,38.1
S$1502  (via drill 1 pad 1.78)
  other vias: 83.82,38.1
S$1503  (via drill 1 pad 1.78)
  other vias: 91.44,45.72
S$1504  (via drill 1 pad 1.78)
  other vias: 96.52,45.72
S$1505  (via drill 1 pad 1.78)
  other vias: 104.14,45.72
S$1506  (via drill 1 pad 1.78)
  other vias: 111.76,48.26
S$1507  (via drill 1 pad 1.78)
  other vias: 111.76,45.72
S$1508  (via drill 1 pad 1.78)
  other vias: 106.68,45.72
S$1509  (via drill 1 pad 1.78)
  other vias: 106.68,43.18
S$1510  (via drill 1 pad 1.78)
  other vias: 104.14,40.64
S$1511  (via drill 1 pad 1.78)
  other vias: 96.52,40.64
S$1512  (via drill 1 pad 1.78)
  other vias: 88.9,38.1
S$1513  (via drill 1 pad 1.78)
  other vias: 88.9,35.56
S$1514  (via drill 1 pad 1.78)
  other vias: 86.36,35.56
S$1515  (via drill 1 pad 1.78)
  other vias: 81.28,30.48
S$1516  (via drill 1 pad 1.78)
  other vias: 81.28,25.4
S$1517  (via drill 1 pad 1.78)
  other vias: 78.74,25.4
S$1518  (via drill 1 pad 1.78)
  other vias: 81.28,22.86
S$1519  (via drill 1 pad 1.78)
  other vias: 83.82,22.86
S$1520  (via drill 1 pad 1.78)
  other vias: 86.36,25.4
S$1521  (via drill 1 pad 1.78)
  other vias: 88.9,25.4
S$1522  (via drill 1 pad 1.78)
  other vias: 88.9,22.86
S$1523  (via drill 1 pad 1.78)
  other vias: 91.44,22.86
S$1524  (via drill 1 pad 1.78)
  other vias: 91.44,27.94
S$1525  (via drill 1 pad 1.78)
  other vias: 88.9,30.48
S$1526  (via drill 1 pad 1.78)
  other vias: 91.44,33.02
S$1527  (via drill 1 pad 1.78)
  other vias: 93.98,35.56
S$1528  (via drill 1 pad 1.78)
  other vias: 93.98,30.48
S$1529  (via drill 1 pad 1.78)
  other vias: 93.98,25.4
S$1530  (via drill 1 pad 1.78)
  other vias: 96.52,33.02
S$1531  (via drill 1 pad 1.78)
  other vias: 96.52,30.48
S$1532  (via drill 1 pad 1.78)
  other vias: 96.52,27.94
S$1533  (via drill 1 pad 1.78)
  other vias: 96.52,22.86
S$1534  (via drill 1 pad 1.78)
  other vias: 96.52,20.32
S$1535  (via drill 1 pad 1.78)
  other vias: 99.06,22.86
S$1536  (via drill 1 pad 1.78)
  other vias: 99.06,25.4
S$1537  (via drill 1 pad 1.78)
  other vias: 99.06,27.94
S$1538  (via drill 1 pad 1.78)
  other vias: 99.06,33.02
S$1539  (via drill 1 pad 1.78)
  other vias: 101.6,35.56
S$1540  (via drill 1 pad 1.78)
  other vias: 101.6,25.4
S$1541  (via drill 1 pad 1.78)
  other vias: 101.6,20.32
S$1542  (via drill 1 pad 1.78)
  other vias: 106.68,20.32
S$1543  (via drill 1 pad 1.78)
  other vias: 106.68,22.86
S$1544  (via drill 1 pad 1.78)
  other vias: 104.14,30.48
S$1545  (via drill 1 pad 1.78)
  other vias: 104.14,33.02
S$1546  (via drill 1 pad 1.78)
  other vias: 106.68,38.1
S$1547  (via drill 1 pad 1.78)
  other vias: 106.68,35.56
S$1548  (via drill 1 pad 1.78)
  other vias: 106.68,33.02
S$1549  (via drill 1 pad 1.78)
  other vias: 109.22,35.56
S$1550  (via drill 1 pad 1.78)
  other vias: 109.22,30.48
S$1551  (via drill 1 pad 1.78)
  other vias: 109.22,27.94
S$1552  (via drill 1 pad 1.78)
  other vias: 119.38,35.56
S$1553  (via drill 1 pad 1.78)
  other vias: 124.46,35.56
S$1554  (via drill 1 pad 1.78)
  other vias: 121.92,35.56
S$1555  (via drill 1 pad 1.78)
  other vias: 127,35.56
S$1556  (via drill 1 pad 1.78)
  other vias: 132.08,35.56
S$1557  (via drill 1 pad 1.78)
  other vias: 137.16,35.56
S$1558  (via drill 1 pad 1.78)
  other vias: 139.7,35.56
S$1559  (via drill 1 pad 1.78)
  other vias: 142.24,35.56
S$1560  (via drill 1 pad 1.78)
  other vias: 142.24,38.1
S$1561  (via drill 1 pad 1.78)
  other vias: 134.62,35.56
S$1562  (via drill 1 pad 1.78)
  other vias: 134.62,38.1
S$1563  (via drill 1 pad 1.78)
  other vias: 134.62,40.64
S$1564  (via drill 1 pad 1.78)
  other vias: 132.08,48.26
S$1565  (via drill 1 pad 1.78)
  other vias: 132.08,45.72
S$1566  (via drill 1 pad 1.78)
  other vias: 132.08,43.18
S$1567  (via drill 1 pad 1.78)
  other vias: 129.54,40.64
S$1568  (via drill 1 pad 1.78)
  other vias: 129.54,35.56
S$1569  (via drill 1 pad 1.78)
  other vias: 129.54,30.48
S$1570  (via drill 1 pad 1.78)
  other vias: 129.54,33.02
S$1571  (via drill 1 pad 1.78)
  other vias: 132.08,30.48
S$1572  (via drill 1 pad 1.78)
  other vias: 132.08,27.94
S$1573  (via drill 1 pad 1.78)
  other vias: 132.08,25.4
S$1574  (via drill 1 pad 1.78)
  other vias: 134.62,27.94
S$1575  (via drill 1 pad 1.78)
  other vias: 134.62,25.4
S$1576  (via drill 1 pad 1.78)
  other vias: 137.16,33.02
S$1577  (via drill 1 pad 1.78)
  other vias: 137.16,30.48
S$1578  (via drill 1 pad 1.78)
  other vias: 137.16,27.94
S$1579  (via drill 1 pad 1.78)
  other vias: 139.7,30.48
S$1580  (via drill 1 pad 1.78)
  other vias: 139.7,27.94
S$1581  (via drill 1 pad 1.78)
  other vias: 139.7,25.4
S$1582  (via drill 1 pad 1.78)
  other vias: 142.24,27.94
S$1583  (via drill 1 pad 1.78)
  other vias: 144.78,30.48
S$1584  (via drill 1 pad 1.78)
  other vias: 142.24,33.02
S$1585  (via drill 1 pad 1.78)
  other vias: 144.78,38.1
S$1586  (via drill 1 pad 1.78)
  other vias: 139.7,45.72
S$1587  (via drill 1 pad 1.78)
  other vias: 139.7,43.18
S$1588  (via drill 1 pad 1.78)
  other vias: 139.7,40.64
S$1589  (via drill 1 pad 1.78)
  other vias: 142.24,45.72
S$1590  (via drill 1 pad 1.78)
  other vias: 137.16,45.72
S$1591  (via drill 1 pad 1.78)
  other vias: 137.16,40.64
S$1592  (via drill 1 pad 1.78)
  other vias: 134.62,43.18
S$1593  (via drill 1 pad 1.78)
  other vias: 121.92,38.1
S$1594  (via drill 1 pad 1.78)
  other vias: 119.38,30.48
S$1595  (via drill 1 pad 1.78)
  other vias: 121.92,30.48
S$1596  (via drill 1 pad 1.78)
  other vias: 124.46,30.48
S$1597  (via drill 1 pad 1.78)
  other vias: 127,30.48
S$1598  (via drill 1 pad 1.78)
  other vias: 124.46,33.02
S$1599  (via drill 1 pad 1.78)
  other vias: 119.38,33.02
S$1600  (via drill 1 pad 1.78)
  other vias: 116.84,33.02
S$1601  (via drill 1 pad 1.78)
  other vias: 114.3,35.56
S$1602  (via drill 1 pad 1.78)
  other vias: 114.3,43.18
S$1603  (via drill 1 pad 1.78)
  other vias: 114.3,30.48
S$1604  (via drill 1 pad 1.78)
  other vias: 116.84,27.94
S$1605  (via drill 1 pad 1.78)
  other vias: 119.38,25.4
S$1606  (via drill 1 pad 1.78)
  other vias: 121.92,27.94
S$1607  (via drill 1 pad 1.78)
  other vias: 124.46,25.4
S$1608  (via drill 1 pad 1.78)
  other vias: 127,25.4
